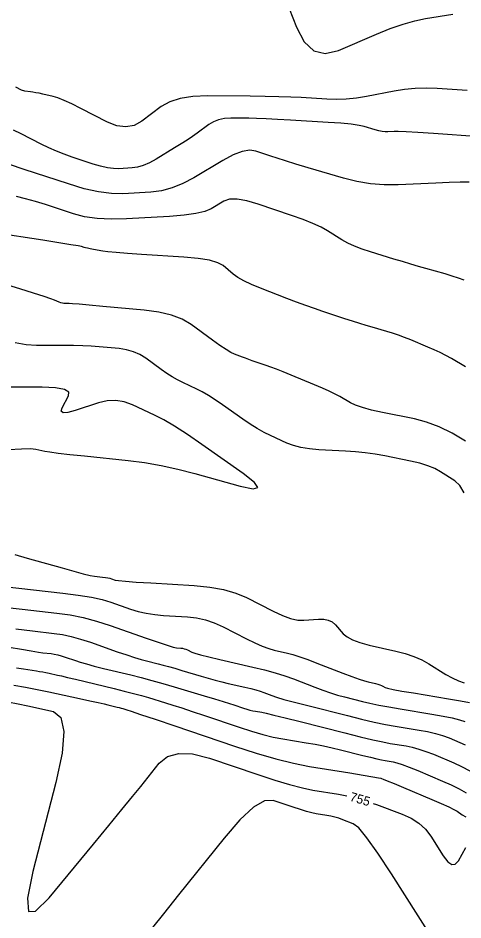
# Model space of a CAD drawing. Extents: x 2082232 to 2083549, y 592624 to 593832.
# Drawn here: x 2082269.1 to 2082303.3, y 592822.8 to 592892.1 of the extents above; entities that cross this region are included whole.
import ezdxf

# ---------------------------------------------------------------- set-up
doc = ezdxf.new("R2010")
doc.units = 0
doc.layers.add('DT_X_Contour_Major', color=7, linetype='Continuous')
doc.layers.add('DT_X_Contour_Minor', color=7, linetype='Continuous')

msp = doc.modelspace()

# ---------------------------------------------------------------- linework, layer by layer
at = {"layer": 'DT_X_Contour_Major'}
for points in [[(2082289.1, 592894.977), (2082290.502, 592891.36), (2082291.098, 592890.232), (2082291.837, 592889.559), (2082292.717, 592889.343), (2082293.739, 592889.582), (2082296.653, 592890.828), (2082297.708, 592891.253), (2082298.686, 592891.594), (2082299.589, 592891.851), (2082300.416, 592892.024), (2082302.518, 592892.373)], [(2082303.48, 592865.288), (2082302.397, 592865.929), (2082301.98, 592866.164), (2082301.541, 592866.39), (2082301.08, 592866.607), (2082300.598, 592866.815), (2082299.283, 592867.356), (2082298.798, 592867.549), (2082298.33, 592867.721), (2082297.88, 592867.873), (2082297.447, 592868.004), (2082296.316, 592868.327), (2082295.866, 592868.459), (2082295.366, 592868.614), (2082294.814, 592868.79), (2082294.211, 592868.989), (2082292.535, 592869.548), (2082291.891, 592869.768), (2082291.215, 592870.008), (2082290.507, 592870.269), (2082289.767, 592870.551), (2082287.752, 592871.329), (2082287.054, 592871.615), (2082286.472, 592871.889), (2082286.006, 592872.153), (2082285.655, 592872.405), (2082284.875, 592873.061), (2082284.467, 592873.286), (2082283.828, 592873.469), (2082282.96, 592873.61), (2082281.86, 592873.709), (2082278.621, 592873.917), (2082277.524, 592873.992), (2082276.663, 592874.06), (2082276.038, 592874.121), (2082275.648, 592874.175), (2082274.923, 592874.31), (2082274.675, 592874.358), (2082274.475, 592874.399), (2082274.322, 592874.433), (2082274.217, 592874.461), (2082274.001, 592874.526), (2082273.755, 592874.575), (2082273.178, 592874.67), (2082272.271, 592874.814), (2082271.033, 592875.004), (2082267.293, 592875.576)], [(2082268.53, 592846.796), (2082269.448, 592846.691), (2082272.119, 592846.392), (2082273.125, 592846.248), (2082274.14, 592846.041), (2082275.163, 592845.772), (2082276.194, 592845.439), (2082278.956, 592844.468), (2082279.879, 592844.149), (2082280.574, 592843.918), (2082281.044, 592843.777), (2082281.286, 592843.725), (2082281.63, 592843.704), (2082281.759, 592843.689), (2082281.887, 592843.66), (2082282.015, 592843.617), (2082282.141, 592843.559), (2082282.478, 592843.387), (2082282.707, 592843.304), (2082283.141, 592843.182), (2082283.78, 592843.022), (2082284.624, 592842.824), (2082287.148, 592842.244), (2082288.054, 592842.024), (2082288.877, 592841.799), (2082289.617, 592841.568), (2082290.275, 592841.333), (2082291.921, 592840.697), (2082292.526, 592840.472), (2082293.106, 592840.273), (2082293.662, 592840.102), (2082294.194, 592839.956), (2082295.579, 592839.605), (2082296.149, 592839.471), (2082296.818, 592839.333), (2082297.588, 592839.189), (2082298.457, 592839.041), (2082300.908, 592838.641), (2082301.755, 592838.492), (2082302.455, 592838.345), (2082303.009, 592838.201), (2082303.417, 592838.06)], [(2082268.362, 592839.569), (2082269.133, 592839.422), (2082269.884, 592839.265), (2082271.861, 592838.834), (2082272.427, 592838.372), (2082272.643, 592837.311), (2082272.51, 592835.651), (2082272.027, 592833.39), (2082270.272, 592826.563), (2082269.856, 592824.516), (2082269.925, 592823.496), (2082270.477, 592823.503), (2082271.513, 592824.536), (2082274.922, 592828.659), (2082276.107, 592830.095), (2082277.106, 592831.312), (2082277.919, 592832.308), (2082278.546, 592833.084), (2082279.969, 592834.86), (2082280.609, 592835.383), (2082281.464, 592835.623), (2082282.534, 592835.578), (2082283.818, 592835.249), (2082287.527, 592833.992), (2082288.835, 592833.565), (2082289.979, 592833.226), (2082290.958, 592832.974), (2082291.772, 592832.811), (2082293.722, 592832.491), (2082294.384, 592832.365)], [(2082296.401, 592831.786), (2082296.656, 592831.697), (2082298.619, 592830.956), (2082299.308, 592830.642), (2082299.903, 592830.256), (2082300.405, 592829.797), (2082300.814, 592829.265), (2082301.778, 592827.751), (2082302.121, 592827.302), (2082302.428, 592827.091), (2082302.698, 592827.116), (2082302.932, 592827.38), (2082303.508, 592828.398)]]:
    msp.add_lwpolyline(points, dxfattribs=at)
at = {"layer": 'DT_X_Contour_Minor'}
for points in [[(2082303.597, 592886.512), (2082301.304, 592886.652), (2082300.453, 592886.68), (2082299.618, 592886.656), (2082298.8, 592886.581), (2082297.999, 592886.455), (2082295.886, 592886.051), (2082295.101, 592885.924), (2082294.33, 592885.847), (2082293.573, 592885.818), (2082292.83, 592885.839), (2082290.868, 592885.959), (2082290.072, 592885.999), (2082289.154, 592886.031), (2082288.115, 592886.054), (2082286.955, 592886.068), (2082283.698, 592886.093), (2082282.559, 592886.049), (2082281.585, 592885.897), (2082280.776, 592885.638), (2082280.132, 592885.271), (2082278.634, 592884.149), (2082278.047, 592883.829), (2082277.411, 592883.712), (2082276.724, 592883.797), (2082275.989, 592884.085), (2082273.96, 592885.123), (2082273.256, 592885.472), (2082272.667, 592885.741), (2082272.193, 592885.93), (2082271.834, 592886.039), (2082271.029, 592886.224), (2082270.745, 592886.287), (2082270.494, 592886.337), (2082270.276, 592886.373), (2082270.093, 592886.397), (2082269.65, 592886.442), (2082269.396, 592886.531), (2082268.966, 592886.765)], [(2082304.581, 592882.96), (2082301.023, 592883.193), (2082299.833, 592883.269), (2082298.932, 592883.321), (2082298.318, 592883.348), (2082297.994, 592883.352), (2082297.512, 592883.329), (2082297.316, 592883.333), (2082297.087, 592883.363), (2082296.827, 592883.417), (2082296.535, 592883.496), (2082295.714, 592883.74), (2082295.31, 592883.828), (2082294.711, 592883.91), (2082293.92, 592883.986), (2082292.935, 592884.055), (2082290.049, 592884.232), (2082289.038, 592884.291), (2082288.168, 592884.333), (2082287.438, 592884.361), (2082286.85, 592884.373), (2082285.47, 592884.383), (2082284.975, 592884.356), (2082284.527, 592884.265), (2082284.125, 592884.111), (2082283.769, 592883.893), (2082282.882, 592883.229), (2082282.524, 592882.971), (2082282.117, 592882.696), (2082281.66, 592882.403), (2082281.154, 592882.094), (2082279.736, 592881.244), (2082279.223, 592880.963), (2082278.747, 592880.755), (2082278.307, 592880.622), (2082277.904, 592880.563), (2082276.878, 592880.504), (2082276.465, 592880.509), (2082275.998, 592880.571), (2082275.475, 592880.687), (2082274.898, 592880.86), (2082273.284, 592881.394), (2082272.682, 592881.606), (2082272.085, 592881.843), (2082271.495, 592882.104), (2082270.911, 592882.389), (2082269.36, 592883.182), (2082268.794, 592883.469)], [(2082303.758, 592879.461), (2082303.07, 592879.461), (2082302.223, 592879.44), (2082301.215, 592879.4), (2082298.317, 592879.265), (2082297.239, 592879.258), (2082296.179, 592879.34), (2082295.137, 592879.509), (2082294.114, 592879.767), (2082291.409, 592880.571), (2082290.468, 592880.854), (2082289.674, 592881.097), (2082289.028, 592881.301), (2082288.528, 592881.466), (2082287.392, 592881.855), (2082286.914, 592881.92), (2082286.333, 592881.822), (2082285.649, 592881.563), (2082284.862, 592881.141), (2082282.626, 592879.801), (2082281.791, 592879.355), (2082280.962, 592879.024), (2082280.142, 592878.806), (2082279.328, 592878.702), (2082277.168, 592878.578), (2082276.299, 592878.59), (2082275.315, 592878.719), (2082274.215, 592878.965), (2082272.999, 592879.328), (2082269.601, 592880.453), (2082268.472, 592880.829)], [(2082303.386, 592871.948), (2082302.939, 592872.105), (2082302.45, 592872.263), (2082301.919, 592872.421), (2082300.444, 592872.841), (2082299.876, 592873.005), (2082299.276, 592873.181), (2082298.647, 592873.369), (2082297.987, 592873.569), (2082296.185, 592874.117), (2082295.541, 592874.33), (2082294.962, 592874.556), (2082294.447, 592874.795), (2082293.996, 592875.047), (2082292.88, 592875.738), (2082292.394, 592876.006), (2082291.773, 592876.291), (2082291.017, 592876.593), (2082290.127, 592876.912), (2082287.572, 592877.786), (2082286.688, 592878.046), (2082285.952, 592878.169), (2082285.365, 592878.155), (2082284.926, 592878.005), (2082283.953, 592877.422), (2082283.479, 592877.221), (2082282.788, 592877.058), (2082281.879, 592876.932), (2082280.752, 592876.842), (2082277.458, 592876.652), (2082276.276, 592876.623), (2082275.204, 592876.678), (2082274.24, 592876.817), (2082273.385, 592877.04), (2082271.249, 592877.747), (2082270.466, 592877.992), (2082269.718, 592878.195), (2082269.005, 592878.358)], [(2082303.491, 592859.594), (2082302.464, 592860.199), (2082301.466, 592860.683), (2082300.499, 592861.049), (2082299.563, 592861.295), (2082297.106, 592861.792), (2082296.261, 592861.978), (2082295.569, 592862.163), (2082295.031, 592862.346), (2082294.645, 592862.529), (2082293.822, 592863.013), (2082293.469, 592863.206), (2082293.027, 592863.422), (2082292.497, 592863.662), (2082291.878, 592863.924), (2082290.109, 592864.654), (2082289.492, 592864.906), (2082288.966, 592865.114), (2082288.532, 592865.279), (2082288.19, 592865.4), (2082287.4, 592865.664), (2082287.112, 592865.761), (2082286.842, 592865.856), (2082286.589, 592865.947), (2082286.354, 592866.036), (2082285.751, 592866.269), (2082285.476, 592866.401), (2082285.103, 592866.624), (2082284.633, 592866.937), (2082284.065, 592867.34), (2082282.42, 592868.536), (2082281.733, 592868.941), (2082280.903, 592869.262), (2082279.93, 592869.497), (2082278.816, 592869.647), (2082275.654, 592869.934), (2082274.603, 592870.028), (2082273.821, 592870.095), (2082273.308, 592870.135), (2082273.064, 592870.149), (2082272.771, 592870.148), (2082272.658, 592870.155), (2082272.54, 592870.177), (2082272.415, 592870.213), (2082272.285, 592870.263), (2082271.929, 592870.416), (2082271.662, 592870.513), (2082271.128, 592870.687), (2082270.327, 592870.939), (2082269.26, 592871.269), (2082266.057, 592872.253)], [(2082303.378, 592855.62), (2082303.039, 592856.181), (2082302.654, 592856.54), (2082301.568, 592857.232), (2082301.119, 592857.477), (2082300.586, 592857.696), (2082299.968, 592857.887), (2082299.266, 592858.051), (2082297.283, 592858.452), (2082296.537, 592858.589), (2082295.786, 592858.698), (2082295.03, 592858.778), (2082294.268, 592858.831), (2082292.232, 592858.934), (2082291.505, 592858.995), (2082290.85, 592859.101), (2082290.269, 592859.25), (2082289.76, 592859.444), (2082288.502, 592860.021), (2082288.015, 592860.262), (2082287.5, 592860.552), (2082286.957, 592860.892), (2082286.384, 592861.282), (2082284.82, 592862.387), (2082284.257, 592862.772), (2082283.741, 592863.101), (2082283.271, 592863.373), (2082282.849, 592863.587), (2082281.786, 592864.083), (2082281.382, 592864.286), (2082280.968, 592864.523), (2082280.543, 592864.793), (2082280.108, 592865.096), (2082278.933, 592865.95), (2082278.475, 592866.237), (2082277.983, 592866.457), (2082277.456, 592866.61), (2082276.895, 592866.696), (2082275.353, 592866.835), (2082274.749, 592866.881), (2082274.095, 592866.914), (2082273.391, 592866.933), (2082272.637, 592866.939), (2082270.557, 592866.937), (2082269.756, 592866.988), (2082268.913, 592867.14)], [(2082268.413, 592858.942), (2082269.394, 592859.001), (2082270.087, 592859.014), (2082270.492, 592858.98), (2082271.191, 592858.826), (2082271.577, 592858.759), (2082272.212, 592858.674), (2082273.097, 592858.571), (2082274.23, 592858.45), (2082277.585, 592858.102), (2082278.848, 592857.943), (2082280.123, 592857.725), (2082281.409, 592857.449), (2082282.707, 592857.115), (2082286.181, 592856.146), (2082287.173, 592855.933), (2082287.542, 592856.021), (2082287.289, 592856.408), (2082286.414, 592857.096), (2082283.251, 592859.33), (2082282.134, 592860.1), (2082281.155, 592860.734), (2082280.315, 592861.233), (2082279.613, 592861.596), (2082277.925, 592862.383), (2082277.287, 592862.614), (2082276.639, 592862.715), (2082275.98, 592862.686), (2082275.312, 592862.527), (2082273.515, 592861.932), (2082272.948, 592861.779), (2082272.594, 592861.766), (2082272.454, 592861.892), (2082272.528, 592862.159), (2082273.01, 592863.057), (2082273.02, 592863.351), (2082272.687, 592863.561), (2082272.011, 592863.687), (2082270.993, 592863.728), (2082267.822, 592863.726)], [(2082268.883, 592850.89), (2082269.846, 592850.618), (2082272.515, 592849.855), (2082273.42, 592849.601), (2082274.135, 592849.413), (2082274.659, 592849.289), (2082274.992, 592849.23), (2082275.625, 592849.159), (2082275.846, 592849.131), (2082276.035, 592849.1), (2082276.191, 592849.066), (2082276.314, 592849.03), (2082276.6, 592848.93), (2082276.85, 592848.888), (2082277.386, 592848.836), (2082278.209, 592848.774), (2082279.318, 592848.704), (2082282.655, 592848.503), (2082283.846, 592848.388), (2082284.913, 592848.196), (2082285.857, 592847.925), (2082286.679, 592847.576), (2082288.705, 592846.542), (2082289.423, 592846.207), (2082290.056, 592845.978), (2082290.605, 592845.855), (2082291.07, 592845.838), (2082292.197, 592845.934), (2082292.595, 592845.933), (2082292.944, 592845.859), (2082293.244, 592845.712), (2082293.494, 592845.491), (2082294.095, 592844.806), (2082294.389, 592844.559), (2082294.817, 592844.332), (2082295.381, 592844.127), (2082296.08, 592843.941), (2082298.125, 592843.474), (2082298.858, 592843.283), (2082299.524, 592843.058), (2082300.123, 592842.8), (2082300.655, 592842.509), (2082301.983, 592841.69), (2082302.469, 592841.412), (2082302.931, 592841.196), (2082303.369, 592841.039)], [(2082268.076, 592848.426), (2082269.195, 592848.299), (2082272.576, 592847.92), (2082273.757, 592847.771), (2082274.763, 592847.607), (2082275.596, 592847.428), (2082276.254, 592847.235), (2082277.778, 592846.699), (2082278.364, 592846.518), (2082278.98, 592846.377), (2082279.626, 592846.276), (2082280.302, 592846.214), (2082282.143, 592846.103), (2082282.831, 592846.024), (2082283.516, 592845.868), (2082284.198, 592845.637), (2082284.875, 592845.33), (2082286.678, 592844.41), (2082287.316, 592844.098), (2082287.882, 592843.849), (2082288.373, 592843.665), (2082288.791, 592843.546), (2082289.806, 592843.313), (2082290.233, 592843.2), (2082290.753, 592843.036), (2082291.365, 592842.822), (2082292.071, 592842.557), (2082294.075, 592841.782), (2082294.759, 592841.522), (2082295.308, 592841.322), (2082295.722, 592841.183), (2082296.001, 592841.105), (2082296.564, 592840.976), (2082296.757, 592840.929), (2082296.916, 592840.882), (2082297.039, 592840.837), (2082297.126, 592840.793), (2082297.313, 592840.678), (2082297.501, 592840.62), (2082297.925, 592840.53), (2082298.583, 592840.411), (2082299.478, 592840.261), (2082302.177, 592839.82), (2082303.089, 592839.664), (2082303.8, 592839.528)], [(2082268.963, 592845.187), (2082269.611, 592845.098), (2082270.24, 592845.022), (2082271.894, 592844.837), (2082272.533, 592844.742), (2082273.211, 592844.596), (2082273.928, 592844.4), (2082274.684, 592844.153), (2082276.752, 592843.426), (2082277.473, 592843.177), (2082278.085, 592842.976), (2082278.589, 592842.822), (2082278.985, 592842.716), (2082279.896, 592842.495), (2082280.264, 592842.402), (2082280.687, 592842.288), (2082281.164, 592842.153), (2082281.695, 592841.997), (2082283.184, 592841.552), (2082283.733, 592841.393), (2082284.263, 592841.247), (2082284.774, 592841.115), (2082285.266, 592840.998), (2082286.551, 592840.703), (2082287.003, 592840.594), (2082287.393, 592840.491), (2082287.722, 592840.392), (2082287.99, 592840.298), (2082288.622, 592840.053), (2082288.972, 592839.937), (2082289.548, 592839.771), (2082290.35, 592839.556), (2082291.378, 592839.292), (2082294.42, 592838.52), (2082295.504, 592838.253), (2082296.476, 592838.03), (2082297.334, 592837.851), (2082298.079, 592837.717), (2082299.916, 592837.417), (2082300.576, 592837.294), (2082301.179, 592837.151), (2082301.726, 592836.988), (2082302.215, 592836.805), (2082303.445, 592836.291)], [(2082268.444, 592843.774), (2082269.397, 592843.61), (2082270.146, 592843.485), (2082270.691, 592843.4), (2082271.032, 592843.353), (2082271.668, 592843.282), (2082271.914, 592843.246), (2082272.175, 592843.19), (2082272.45, 592843.114), (2082272.741, 592843.019), (2082273.536, 592842.74), (2082273.895, 592842.624), (2082274.376, 592842.487), (2082274.978, 592842.329), (2082275.703, 592842.15), (2082277.796, 592841.643), (2082278.591, 592841.444), (2082279.408, 592841.227), (2082280.246, 592840.994), (2082281.106, 592840.743), (2082283.426, 592840.051), (2082284.221, 592839.812), (2082284.867, 592839.615), (2082285.363, 592839.46), (2082285.71, 592839.347), (2082286.435, 592839.101), (2082286.697, 592839.017), (2082286.936, 592838.948), (2082287.154, 592838.895), (2082287.35, 592838.857), (2082287.844, 592838.776), (2082288.167, 592838.708), (2082288.765, 592838.567), (2082289.638, 592838.352), (2082290.786, 592838.063), (2082294.214, 592837.194), (2082295.396, 592836.899), (2082296.371, 592836.668), (2082297.14, 592836.498), (2082297.701, 592836.392), (2082298.923, 592836.193), (2082299.397, 592836.096), (2082299.903, 592835.957), (2082300.442, 592835.776), (2082301.013, 592835.551), (2082302.579, 592834.896), (2082303.181, 592834.618), (2082303.813, 592834.279)], [(2082269.015, 592842.194), (2082269.547, 592842.105), (2082269.888, 592842.051), (2082270.542, 592841.954), (2082270.787, 592841.915), (2082271.031, 592841.872), (2082271.274, 592841.826), (2082271.516, 592841.775), (2082272.16, 592841.635), (2082272.475, 592841.564), (2082272.936, 592841.456), (2082273.543, 592841.311), (2082274.296, 592841.129), (2082276.5, 592840.595), (2082277.285, 592840.401), (2082277.986, 592840.221), (2082278.605, 592840.054), (2082279.141, 592839.9), (2082280.459, 592839.507), (2082281.016, 592839.335), (2082281.698, 592839.117), (2082282.506, 592838.85), (2082283.44, 592838.537), (2082286.097, 592837.636), (2082287.053, 592837.327), (2082287.93, 592837.075), (2082288.728, 592836.879), (2082289.446, 592836.739), (2082291.255, 592836.443), (2082291.929, 592836.326), (2082292.592, 592836.196), (2082293.245, 592836.053), (2082293.889, 592835.897), (2082295.591, 592835.466), (2082296.178, 592835.32), (2082296.663, 592835.204), (2082297.044, 592835.12), (2082297.323, 592835.068), (2082297.93, 592834.969), (2082298.218, 592834.899), (2082298.628, 592834.763), (2082299.159, 592834.563), (2082299.811, 592834.297), (2082301.713, 592833.501), (2082302.391, 592833.202), (2082302.997, 592832.902), (2082303.532, 592832.602)], [(2082268.816, 592840.861), (2082269.71, 592840.705), (2082270.601, 592840.534), (2082271.489, 592840.348), (2082273.85, 592839.833), (2082274.649, 592839.658), (2082275.277, 592839.519), (2082275.733, 592839.417), (2082276.016, 592839.351), (2082276.544, 592839.223), (2082276.732, 592839.177), (2082276.9, 592839.133), (2082277.048, 592839.093), (2082277.176, 592839.056), (2082277.492, 592838.962), (2082277.81, 592838.859), (2082278.529, 592838.618), (2082279.649, 592838.24), (2082281.169, 592837.726), (2082285.758, 592836.171), (2082287.408, 592835.638), (2082288.918, 592835.202), (2082290.288, 592834.865), (2082291.517, 592834.626), (2082294.609, 592834.12), (2082295.626, 592833.953), (2082296.359, 592833.832), (2082296.807, 592833.755), (2082296.972, 592833.724), (2082297.032, 592833.701), (2082297.153, 592833.651), (2082297.474, 592833.518), (2082297.993, 592833.301), (2082298.711, 592833), (2082300.891, 592832.087), (2082301.625, 592831.775), (2082302.193, 592831.521), (2082302.594, 592831.326), (2082302.828, 592831.19), (2082303.231, 592830.907), (2082303.502, 592830.749)], [(2082300.869, 592821.53), (2082297.789, 592826.367), (2082296.74, 592827.969), (2082295.904, 592829.145), (2082295.28, 592829.897), (2082294.868, 592830.225), (2082294.053, 592830.532), (2082293.748, 592830.639), (2082293.443, 592830.73), (2082293.139, 592830.804), (2082292.835, 592830.862), (2082292.026, 592830.995), (2082291.688, 592831.063), (2082291.282, 592831.167), (2082290.807, 592831.308), (2082290.264, 592831.485), (2082288.724, 592832.007), (2082288.055, 592831.973), (2082287.202, 592831.482), (2082286.165, 592830.531), (2082284.945, 592829.123), (2082281.447, 592824.756), (2082280.292, 592823.315), (2082279.453, 592822.268)]]:
    msp.add_lwpolyline(points, dxfattribs=at)

# ---------------------------------------------------------------- texts
at = {"layer": 'DT_X_Contour_Major'}
msp.add_text('755', height=0.7, rotation=343.98512, dxfattribs=at).set_placement((2082294.545, 592831.991))

doc.saveas('drawing.dxf')
